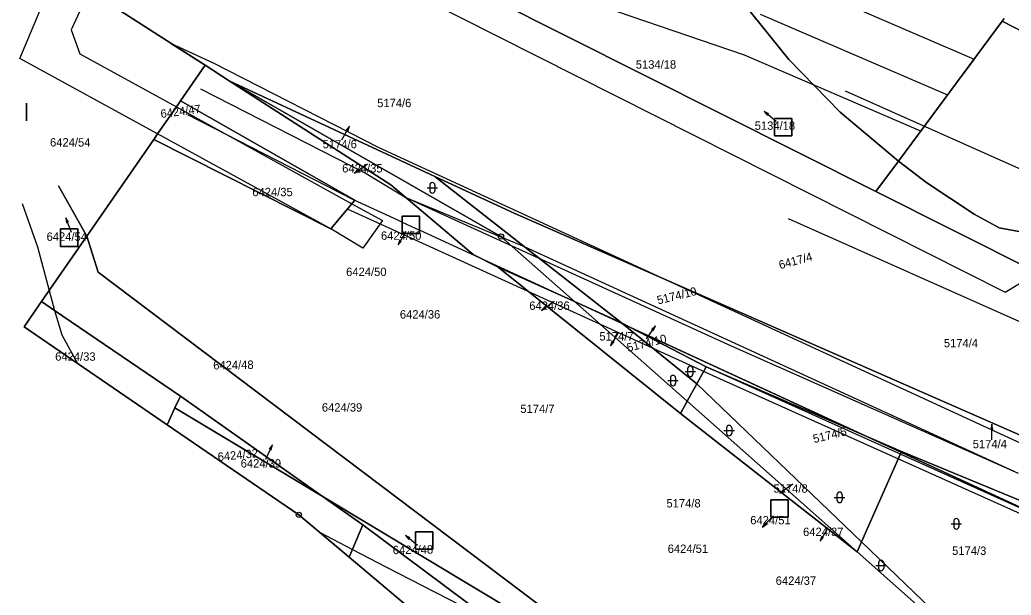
# Model space of a CAD drawing. Extents: x -400488 to -400124, y -1251493 to -1251223.
# Drawn here: x -400488 to -400431, y -1251468.6 to -1251435.6 of the extents above; entities that cross this region are included whole.
import ezdxf

# ---------------------------------------------------------------- set-up
doc = ezdxf.new("R2010")
doc.units = 0
doc.layers.add('Level 63', color=7, linetype='Continuous')

msp = doc.modelspace()

# ---------------------------------------------------------------- linework, layer by layer
at = {"layer": 'Level 63'}
for p, q in [((-400438.81, -1251445.43), (-400473.82, -1251427.84)), ((-400473.82, -1251427.84), (-400438.81, -1251445.43)), ((-400446.35, -1251437.6), (-400471.48, -1251429.02)), ((-400474.92, -1251429.25), (-400431.38, -1251451.21)), ((-400487.96, -1251437.79), (-400485.82, -1251432.73)), ((-400444.55, -1251432.93), (-400433.16, -1251437.83)), ((-400483.98, -1251433.91), (-400485.01, -1251436.16)), ((-400477.32, -1251438.19), (-400483.65, -1251434.12)), ((-400483.65, -1251434.12), (-400477.32, -1251438.19)), ((-400443.8, -1251437.85), (-400446.43, -1251434.61)), ((-400446.43, -1251434.61), (-400443.8, -1251437.85)), ((-400445.45, -1251435.26), (-400434.69, -1251439.89)), ((-400431.55, -1251435.66), (-400437.51, -1251443.68)), ((-400437.51, -1251443.68), (-400431.55, -1251435.66)), ((-400431.55, -1251435.66), (-400431.43, -1251435.5)), ((-400431.43, -1251435.5), (-400431.55, -1251435.66)), ((-400428.79, -1251437.09), (-400431.55, -1251435.66)), ((-400431.55, -1251435.66), (-400428.79, -1251437.09)), ((-400485.01, -1251436.16), (-400484.52, -1251437.53)), ((-400479.3, -1251436.92), (-400477.32, -1251438.19)), ((-400479.3, -1251436.92), (-400476.86, -1251438.04)), ((-400477.32, -1251438.19), (-400479.3, -1251436.92)), ((-400484.52, -1251437.53), (-400478.97, -1251440.58)), ((-400436.23, -1251441.96), (-400446.35, -1251437.6)), ((-400480.05, -1251442.12), (-400487.96, -1251437.79)), ((-400478.73, -1251440.23), (-400477.32, -1251438.19)), ((-400477.32, -1251438.19), (-400478.73, -1251440.23)), ((-400475.93, -1251439.08), (-400477.32, -1251438.19)), ((-400477.32, -1251438.19), (-400475.93, -1251439.08)), ((-400477.32, -1251438.19), (-400475.93, -1251439.08)), ((-400475.93, -1251439.08), (-400477.32, -1251438.19)), ((-400476.86, -1251438.04), (-400467.34, -1251442.9)), ((-400440.85, -1251440.87), (-400443.8, -1251437.85)), ((-400443.8, -1251437.85), (-400440.85, -1251440.87)), ((-400433.16, -1251437.83), (-400434.69, -1251439.89)), ((-400475.93, -1251439.08), (-400464.12, -1251444.57)), ((-400460.33, -1251448.01), (-400475.93, -1251439.08)), ((-400475.93, -1251439.08), (-400460.33, -1251448.01)), ((-400466.65, -1251445.05), (-400475.93, -1251439.08)), ((-400464.12, -1251444.57), (-400475.93, -1251439.08)), ((-400475.93, -1251439.08), (-400466.65, -1251445.05)), ((-400475.93, -1251439.08), (-400464.12, -1251444.57)), ((-400464.12, -1251444.57), (-400475.93, -1251439.08)), ((-400477.59, -1251439.54), (-400468.07, -1251444.4)), ((-400423.96, -1251447.06), (-400440.55, -1251439.68)), ((-400434.69, -1251439.89), (-400436.03, -1251441.69)), ((-400487.57, -1251440.37), (-400487.57, -1251441.37)), ((-400487.57, -1251441.37), (-400487.57, -1251440.37)), ((-400478.97, -1251440.58), (-400478.73, -1251440.23)), ((-400478.73, -1251440.23), (-400478.97, -1251440.58)), ((-400468.72, -1251445.93), (-400478.73, -1251440.23)), ((-400478.73, -1251440.23), (-400468.72, -1251445.93)), ((-400480.05, -1251442.12), (-400478.97, -1251440.58)), ((-400478.97, -1251440.58), (-400480.05, -1251442.12)), ((-400478.97, -1251440.58), (-400468.89, -1251446.13)), ((-400468.8, -1251445.9), (-400478.32, -1251441.04)), ((-400444.52, -1251441.41), (-400445.209, -1251440.831)), ((-400445.209, -1251440.831), (-400445.018, -1251441.07)), ((-400444.941, -1251440.978), (-400445.209, -1251440.831)), ((-400437.51, -1251443.68), (-400440.85, -1251440.87)), ((-400440.85, -1251440.87), (-400437.51, -1251443.68)), ((-400444.62, -1251441.24), (-400444.62, -1251442.24)), ((-400443.62, -1251441.24), (-400444.62, -1251441.24)), ((-400444.62, -1251442.24), (-400444.62, -1251441.24)), ((-400444.62, -1251441.24), (-400443.62, -1251441.24)), ((-400443.62, -1251442.24), (-400443.62, -1251441.24)), ((-400443.62, -1251441.24), (-400443.62, -1251442.24)), ((-400480.27, -1251442.44), (-400480.05, -1251442.12)), ((-400480.05, -1251442.12), (-400480.27, -1251442.44)), ((-400470.11, -1251447.57), (-400480.05, -1251442.12)), ((-400469.47, -1251442.47), (-400469.02, -1251441.69)), ((-400469.02, -1251441.69), (-400469.222, -1251441.92)), ((-400469.118, -1251441.98), (-400469.02, -1251441.69)), ((-400436.03, -1251441.69), (-400436.23, -1251441.96)), ((-400484.12, -1251448), (-400480.27, -1251442.44)), ((-400480.27, -1251442.44), (-400484.12, -1251448)), ((-400480.27, -1251442.44), (-400470.11, -1251447.57)), ((-400470.11, -1251447.57), (-400480.27, -1251442.44)), ((-400444.62, -1251442.24), (-400443.62, -1251442.24)), ((-400443.62, -1251442.24), (-400444.62, -1251442.24)), ((-400467.34, -1251442.9), (-400421.61, -1251463.97)), ((-400468, -1251443.86), (-400468.738, -1251444.376)), ((-400438.81, -1251445.43), (-400437.51, -1251443.68)), ((-400437.51, -1251443.68), (-400438.81, -1251445.43)), ((-400435.88, -1251444.94), (-400437.51, -1251443.68)), ((-400437.51, -1251443.68), (-400435.88, -1251444.94)), ((-400468.526, -1251444.155), (-400468.738, -1251444.376)), ((-400468.738, -1251444.376), (-400468.457, -1251444.253)), ((-400468.07, -1251444.4), (-400465.8, -1251445.77)), ((-400461.93, -1251449.04), (-400466.65, -1251445.05)), ((-400466.65, -1251445.05), (-400461.93, -1251449.04)), ((-400464.42, -1251445.07), (-400464.42, -1251445.37)), ((-400464.12, -1251444.57), (-400459.53, -1251446.7)), ((-400453.4, -1251452.96), (-400464.12, -1251444.57)), ((-400464.12, -1251444.57), (-400453.4, -1251452.96)), ((-400459.53, -1251446.7), (-400464.12, -1251444.57)), ((-400464.12, -1251444.57), (-400458.99, -1251448.58)), ((-400453.4, -1251452.96), (-400464.12, -1251444.57)), ((-400464.12, -1251445.07), (-400464.12, -1251445.37)), ((-400433.16, -1251446.73), (-400435.88, -1251444.94)), ((-400435.88, -1251444.94), (-400433.16, -1251446.73)), ((-400485.73, -1251445.11), (-400484.12, -1251448)), ((-400484.12, -1251448), (-400485.73, -1251445.11)), ((-400464.57, -1251445.22), (-400463.97, -1251445.22)), ((-400429.53, -1251450.09), (-400438.81, -1251445.43)), ((-400438.81, -1251445.43), (-400429.53, -1251450.09)), ((-400487.82, -1251446.11), (-400486.95, -1251448.61)), ((-400470.11, -1251447.57), (-400468.72, -1251445.93)), ((-400468.72, -1251445.93), (-400470.11, -1251447.57)), ((-400468.89, -1251446.13), (-400467.13, -1251447.09)), ((-400466.01, -1251447.19), (-400468.8, -1251445.9)), ((-400465.8, -1251445.77), (-400447.11, -1251454.28)), ((-400465.8, -1251445.77), (-400458.99, -1251448.58)), ((-400458.77, -1251451.16), (-400469.15, -1251446.44)), ((-400459.53, -1251446.7), (-400417.64, -1251465.05)), ((-400417.64, -1251465.05), (-400459.53, -1251446.7)), ((-400431.73, -1251447.52), (-400433.16, -1251446.73)), ((-400433.16, -1251446.73), (-400431.73, -1251447.52)), ((-400485, -1251447.78), (-400485.323, -1251446.94)), ((-400485.323, -1251446.94), (-400485.271, -1251447.241)), ((-400485.159, -1251447.198), (-400485.323, -1251446.94)), ((-400467.13, -1251447.09), (-400468.26, -1251448.69)), ((-400466.01, -1251447.84), (-400466.01, -1251446.84)), ((-400466.01, -1251446.84), (-400465.01, -1251446.84)), ((-400466.01, -1251446.84), (-400466.01, -1251447.84)), ((-400465.01, -1251446.84), (-400466.01, -1251446.84)), ((-400466.01, -1251447.19), (-400465.01, -1251447.65)), ((-400465.01, -1251446.84), (-400465.01, -1251447.84)), ((-400465.01, -1251447.84), (-400465.01, -1251446.84)), ((-400443.83, -1251446.98), (-400427.3, -1251454.33)), ((-400485.63, -1251448.58), (-400485.63, -1251447.58)), ((-400485.63, -1251447.58), (-400484.63, -1251447.58)), ((-400485.63, -1251447.58), (-400485.63, -1251448.58)), ((-400484.63, -1251447.58), (-400485.63, -1251447.58)), ((-400484.63, -1251447.58), (-400484.63, -1251448.58)), ((-400484.63, -1251448.58), (-400484.63, -1251447.58)), ((-400468.26, -1251448.69), (-400470.11, -1251447.57)), ((-400465.79, -1251447.72), (-400466.24, -1251448.499)), ((-400465.01, -1251447.84), (-400466.01, -1251447.84)), ((-400466.01, -1251447.84), (-400465.01, -1251447.84)), ((-400426.03, -1251465.61), (-400465.01, -1251447.65)), ((-400430.6, -1251447.73), (-400431.73, -1251447.52)), ((-400431.73, -1251447.52), (-400430.6, -1251447.73)), ((-400486.71, -1251451.74), (-400484.12, -1251448)), ((-400484.12, -1251448), (-400486.71, -1251451.74)), ((-400483.46, -1251450.05), (-400484.12, -1251448)), ((-400484.12, -1251448), (-400483.46, -1251450.05)), ((-400466.142, -1251448.21), (-400466.24, -1251448.499)), ((-400466.24, -1251448.499), (-400466.038, -1251448.27)), ((-400456.11, -1251451.75), (-400460.33, -1251448.01)), ((-400460.33, -1251448.01), (-400456.11, -1251451.75)), ((-400486.95, -1251448.61), (-400486.28, -1251451.12)), ((-400484.63, -1251448.58), (-400485.63, -1251448.58)), ((-400485.63, -1251448.58), (-400484.63, -1251448.58)), ((-400460.5, -1251449.78), (-400461.93, -1251449.04)), ((-400461.93, -1251449.04), (-400460.5, -1251449.78)), ((-400458.99, -1251448.58), (-400453.4, -1251452.96)), ((-400458.99, -1251448.58), (-400430.64, -1251461.6)), ((-400455.9, -1251470.84), (-400483.46, -1251450.05)), ((-400483.46, -1251450.05), (-400455.9, -1251470.84)), ((-400456.11, -1251451.75), (-400460.5, -1251449.78)), ((-400450.03, -1251458.16), (-400460.5, -1251449.78)), ((-400460.5, -1251449.78), (-400456.11, -1251451.75)), ((-400460.5, -1251449.78), (-400450.03, -1251458.16)), ((-400431.38, -1251451.21), (-400429.53, -1251450.09)), ((-400486.28, -1251451.12), (-400485.96, -1251452.25)), ((-400447.93, -1251456.1), (-400458.77, -1251451.16)), ((-400447.93, -1251456.1), (-400458.77, -1251451.16)), ((-400486.84, -1251451.94), (-400486.71, -1251451.74)), ((-400486.71, -1251451.74), (-400486.84, -1251451.94)), ((-400485.96, -1251452.25), (-400486.71, -1251451.74)), ((-400486.71, -1251451.74), (-400485.96, -1251452.25)), ((-400457.27, -1251451.74), (-400458.008, -1251452.256)), ((-400453.4, -1251452.96), (-400456.11, -1251451.75)), ((-400456.11, -1251451.75), (-400449.64, -1251457.47)), ((-400449.64, -1251457.47), (-400456.11, -1251451.75)), ((-400456.11, -1251451.75), (-400453.4, -1251452.96)), ((-400487.71, -1251453.19), (-400486.84, -1251451.94)), ((-400486.84, -1251451.94), (-400487.71, -1251453.19)), ((-400485.96, -1251452.25), (-400485.55, -1251453.66)), ((-400478.74, -1251457.17), (-400485.96, -1251452.25)), ((-400485.96, -1251452.25), (-400478.74, -1251457.17)), ((-400457.796, -1251452.035), (-400458.008, -1251452.256)), ((-400458.008, -1251452.256), (-400457.727, -1251452.133)), ((-400448.55, -1251455.5), (-400453.4, -1251452.96)), ((-400449.09, -1251456.47), (-400453.4, -1251452.96)), ((-400453.4, -1251452.96), (-400448.55, -1251455.5)), ((-400453.4, -1251452.96), (-400449.09, -1251456.47)), ((-400453.4, -1251452.96), (-400452.81, -1251453.27)), ((-400448.55, -1251455.5), (-400453.4, -1251452.96)), ((-400487.71, -1251453.19), (-400479.49, -1251458.81)), ((-400479.49, -1251458.81), (-400487.71, -1251453.19)), ((-400484.64, -1251455.29), (-400487.71, -1251453.19)), ((-400453.59, -1251453.5), (-400454.04, -1251454.279)), ((-400452.81, -1251453.27), (-400426.03, -1251465.61)), ((-400451.98, -1251453.88), (-400451.464, -1251453.143)), ((-400451.464, -1251453.143), (-400451.685, -1251453.354)), ((-400451.587, -1251453.423), (-400451.464, -1251453.143)), ((-400485.55, -1251453.66), (-400484.64, -1251455.29)), ((-400453.942, -1251453.99), (-400454.04, -1251454.279)), ((-400454.04, -1251454.279), (-400453.838, -1251454.05)), ((-400447.11, -1251454.28), (-400430.64, -1251461.6)), ((-400479.49, -1251458.81), (-400484.64, -1251455.29)), ((-400449.76, -1251455.75), (-400449.16, -1251455.75)), ((-400449.61, -1251455.6), (-400449.61, -1251455.9)), ((-400449.31, -1251455.6), (-400449.31, -1251455.9)), ((-400449.09, -1251456.47), (-400448.55, -1251455.5)), ((-400448.55, -1251455.5), (-400449.09, -1251456.47)), ((-400437.33, -1251460.34), (-400448.55, -1251455.5)), ((-400448.55, -1251455.5), (-400437.33, -1251460.34)), ((-400426.03, -1251465.61), (-400448.55, -1251455.5)), ((-400450.75, -1251456.28), (-400450.15, -1251456.28)), ((-400450.6, -1251456.13), (-400450.6, -1251456.43)), ((-400450.3, -1251456.13), (-400450.3, -1251456.43)), ((-400428.83, -1251464.68), (-400447.93, -1251456.1)), ((-400428.83, -1251464.68), (-400447.93, -1251456.1)), ((-400449.64, -1251457.47), (-400449.09, -1251456.47)), ((-400449.09, -1251456.47), (-400449.64, -1251457.47)), ((-400449.09, -1251456.47), (-400439.63, -1251465.54)), ((-400439.63, -1251465.54), (-400449.09, -1251456.47)), ((-400479.05, -1251457.85), (-400478.74, -1251457.17)), ((-400478.74, -1251457.17), (-400479.05, -1251457.85)), ((-400478.74, -1251457.17), (-400470.59, -1251462.92)), ((-400470.59, -1251462.92), (-400478.74, -1251457.17)), ((-400450.03, -1251458.16), (-400449.64, -1251457.47)), ((-400449.64, -1251457.47), (-400450.03, -1251458.16)), ((-400439.88, -1251466.11), (-400449.64, -1251457.47)), ((-400449.64, -1251457.47), (-400439.88, -1251466.11)), ((-400479.49, -1251458.81), (-400479.05, -1251457.85)), ((-400479.05, -1251457.85), (-400479.49, -1251458.81)), ((-400470.59, -1251462.92), (-400479.05, -1251457.85)), ((-400479.05, -1251457.85), (-400470.59, -1251462.92)), ((-400439.88, -1251466.11), (-400450.03, -1251458.16)), ((-400450.03, -1251458.16), (-400439.88, -1251466.11)), ((-400479.49, -1251458.81), (-400471.94, -1251463.98)), ((-400471.94, -1251463.98), (-400479.49, -1251458.81)), ((-400471.94, -1251463.98), (-400479.49, -1251458.81)), ((-400447.53, -1251459.15), (-400446.93, -1251459.15)), ((-400447.38, -1251459), (-400447.38, -1251459.3)), ((-400447.08, -1251459), (-400447.08, -1251459.3)), ((-400432.14, -1251458.78), (-400432.2, -1251459.08)), ((-400432.14, -1251459.68), (-400432.14, -1251458.78)), ((-400432.08, -1251459.08), (-400432.14, -1251458.78)), ((-400473.84, -1251460.79), (-400473.46, -1251459.974)), ((-400473.46, -1251459.974), (-400473.641, -1251460.221)), ((-400473.533, -1251460.271), (-400473.46, -1251459.974)), ((-400439.63, -1251465.54), (-400437.33, -1251460.34)), ((-400437.33, -1251460.34), (-400439.63, -1251465.54)), ((-400437.33, -1251460.34), (-400418.81, -1251468.02)), ((-400418.81, -1251468.02), (-400437.33, -1251460.34)), ((-400443.57, -1251462.23), (-400444.308, -1251462.746)), ((-400444.096, -1251462.525), (-400444.308, -1251462.746)), ((-400444.308, -1251462.746), (-400444.027, -1251462.623)), ((-400470.59, -1251462.92), (-400446.62, -1251477.3)), ((-400468.27, -1251464.56), (-400470.59, -1251462.92)), ((-400446.62, -1251477.3), (-400470.59, -1251462.92)), ((-400470.59, -1251462.92), (-400468.27, -1251464.56)), ((-400444.84, -1251464.12), (-400444.84, -1251463.12)), ((-400444.84, -1251463.12), (-400443.84, -1251463.12)), ((-400444.84, -1251463.12), (-400444.84, -1251464.12)), ((-400443.84, -1251463.12), (-400444.84, -1251463.12)), ((-400443.84, -1251463.12), (-400443.84, -1251464.12)), ((-400443.84, -1251464.12), (-400443.84, -1251463.12)), ((-400441.19, -1251462.98), (-400440.59, -1251462.98)), ((-400441.04, -1251462.83), (-400441.04, -1251463.13)), ((-400440.74, -1251462.83), (-400440.74, -1251463.13)), ((-400471.94, -1251463.98), (-400469.04, -1251466.41)), ((-400469.04, -1251466.41), (-400471.94, -1251463.98)), ((-400470.75, -1251464.98), (-400471.94, -1251463.98)), ((-400444.69, -1251464.05), (-400445.326, -1251464.687)), ((-400445.156, -1251464.432), (-400445.326, -1251464.687)), ((-400443.84, -1251464.12), (-400444.84, -1251464.12)), ((-400444.84, -1251464.12), (-400443.84, -1251464.12)), ((-400434.33, -1251464.35), (-400434.33, -1251464.65)), ((-400434.03, -1251464.35), (-400434.03, -1251464.65)), ((-400470.75, -1251464.98), (-400468.86, -1251465.97)), ((-400469.04, -1251466.41), (-400470.75, -1251464.98)), ((-400469.04, -1251466.41), (-400468.27, -1251464.56)), ((-400468.27, -1251464.56), (-400469.04, -1251466.41)), ((-400460.85, -1251470.08), (-400468.27, -1251464.56)), ((-400468.27, -1251464.56), (-400460.85, -1251470.08)), ((-400465.24, -1251465.95), (-400465.24, -1251464.95)), ((-400465.24, -1251464.95), (-400464.24, -1251464.95)), ((-400465.24, -1251464.95), (-400465.24, -1251465.95)), ((-400464.24, -1251464.95), (-400465.24, -1251464.95)), ((-400464.24, -1251464.95), (-400464.24, -1251465.95)), ((-400464.24, -1251465.95), (-400464.24, -1251464.95)), ((-400445.326, -1251464.687), (-400445.072, -1251464.517)), ((-400441.56, -1251464.72), (-400442.01, -1251465.499)), ((-400434.48, -1251464.5), (-400433.88, -1251464.5)), ((-400465.13, -1251465.74), (-400465.819, -1251465.161)), ((-400465.819, -1251465.161), (-400465.628, -1251465.4)), ((-400465.551, -1251465.308), (-400465.819, -1251465.161)), ((-400441.912, -1251465.21), (-400442.01, -1251465.499)), ((-400442.01, -1251465.499), (-400441.808, -1251465.27)), ((-400439.88, -1251466.11), (-400439.63, -1251465.54)), ((-400439.63, -1251465.54), (-400439.88, -1251466.11)), ((-400439.63, -1251465.54), (-400428.8, -1251475.91)), ((-400428.8, -1251475.91), (-400439.63, -1251465.54)), ((-400468.86, -1251465.97), (-400466.95, -1251466.97)), ((-400464.24, -1251465.95), (-400465.24, -1251465.95)), ((-400465.24, -1251465.95), (-400464.24, -1251465.95)), ((-400428.8, -1251475.91), (-400439.88, -1251466.11)), ((-400439.88, -1251466.11), (-400428.8, -1251475.91)), ((-400469.04, -1251466.41), (-400456.99, -1251476.54)), ((-400456.99, -1251476.54), (-400469.04, -1251466.41)), ((-400456.99, -1251476.54), (-400469.04, -1251466.41)), ((-400466.95, -1251466.97), (-400460.85, -1251470.08)), ((-400438.8, -1251466.89), (-400438.2, -1251466.89)), ((-400438.65, -1251466.74), (-400438.65, -1251467.04)), ((-400438.35, -1251466.74), (-400438.35, -1251467.04))]:
    msp.add_line(p, q, dxfattribs=at)
for centre, radius in [((-400460.33, -1251448.01), 0.15), ((-400460.33, -1251448.01), 0.03), ((-400471.94, -1251463.98), 0.15), ((-400471.94, -1251463.98), 0.03)]:
    msp.add_circle(centre, radius, dxfattribs=at)
for centre, start, end in [((-400464.27, -1251445.07), 0, 180), ((-400464.27, -1251445.37), 180, 0), ((-400449.46, -1251455.6), 0, 180), ((-400450.45, -1251456.13), 0, 180), ((-400450.45, -1251456.43), 180, 0), ((-400449.46, -1251455.9), 180, 0), ((-400447.23, -1251459), 0, 180), ((-400447.23, -1251459.3), 180, 0), ((-400440.89, -1251462.83), 0, 180), ((-400440.89, -1251463.13), 180, 0), ((-400434.18, -1251464.35), 0, 180), ((-400434.18, -1251464.65), 180, 0), ((-400438.5, -1251466.74), 0, 180), ((-400438.5, -1251467.04), 180, 0)]:
    msp.add_arc(centre, 0.15, start, end, dxfattribs=at)

# ---------------------------------------------------------------- texts
for s, p in [('5134/18', (-400452.59, -1251438.38)), ('5174/6', (-400467.44, -1251440.59)), ('5134/18', (-400445.76, -1251441.89)), ('6424/54', (-400486.224, -1251442.85)), ('5174/6', (-400470.57, -1251442.95)), ('6424/35', (-400469.45, -1251444.34)), ('6424/35', (-400474.61, -1251445.7)), ('6424/54', (-400486.424, -1251448.26)), ('6424/50', (-400467.222, -1251448.2)), ('6424/50', (-400469.222, -1251450.28)), ('6424/36', (-400458.706, -1251452.22)), ('6424/36', (-400466.136, -1251452.72)), ('5174/7', (-400454.678, -1251453.98)), ('5174/4', (-400434.9, -1251454.37)), ('6424/33', (-400485.93, -1251455.14)), ('6424/39', (-400470.616, -1251458.06)), ('5174/7', (-400459.218, -1251458.14)), ('5174/4', (-400433.24, -1251460.16)), ('6424/39', (-400475.276, -1251461.27)), ('5174/8', (-400444.678, -1251462.71)), ('5174/8', (-400450.828, -1251463.56)), ('6424/51', (-400446.016, -1251464.53)), ('6424/37', (-400442.984, -1251465.2)), ('6424/51', (-400450.756, -1251466.17)), ('5174/3', (-400434.424, -1251466.28)), ('6424/37', (-400444.554, -1251468))]:
    msp.add_text(s, height=0.48, dxfattribs=at).set_placement(p)
for s, rotation, p in [('6424/47', 7.33, (-400479.847, -1251441.215)), ('6417/4', 15.29, (-400444.301, -1251449.889)), ('5174/10', 13.82, (-400451.304, -1251451.914)), ('5174/10', 13.82, (-400453.034, -1251454.634)), ('6424/48', 0.96, (-400476.851, -1251455.644)), ('5174/5', 13.76, (-400442.347, -1251459.871)), ('6424/32', 5.55, (-400476.574, -1251460.899)), ('6424/48', 0.96, (-400466.541, -1251466.244))]:
    msp.add_text(s, height=0.48, rotation=rotation, dxfattribs=at).set_placement(p)

doc.saveas('drawing.dxf')
